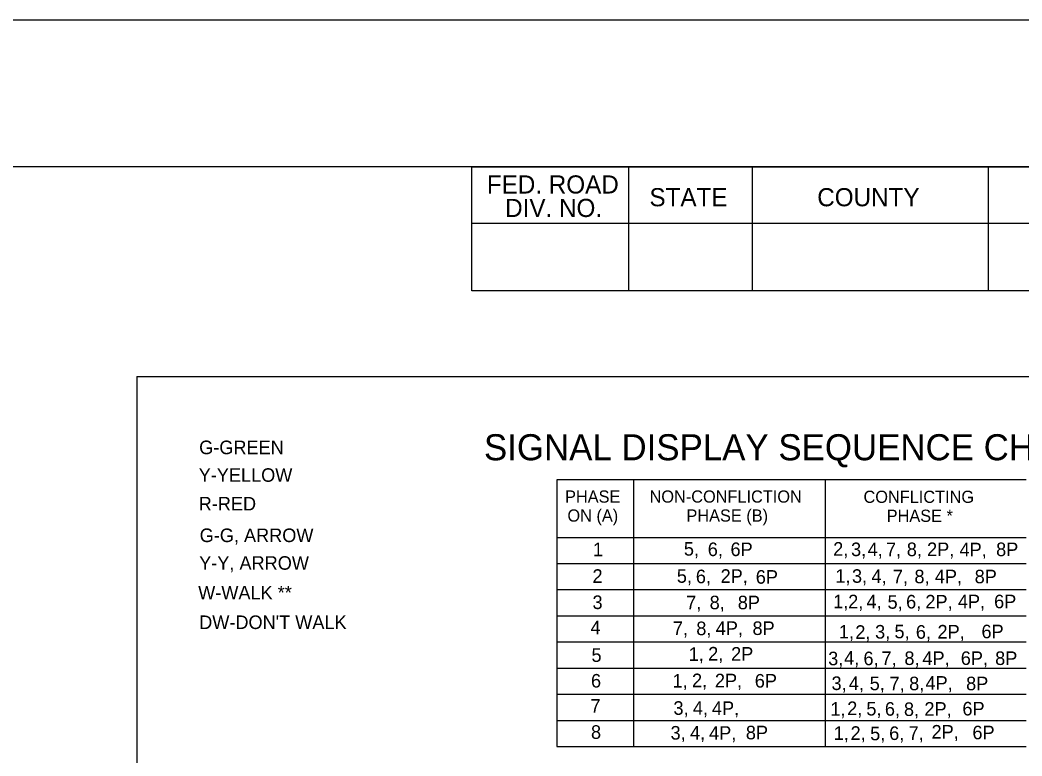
# Model space of a CAD drawing. Extents: x 0 to 3.01, y -0.05 to 1.83.
# Drawn here: x 2.2522 to 2.6475, y 1.5432 to 1.8333 of the extents above; entities that cross this region are included whole.
import ezdxf

# ---------------------------------------------------------------- set-up
doc = ezdxf.new("R2010")
doc.units = 0
for name, color, linetype in [('RD_SHT_IplotShp', 7, 'Continuous'), ('TR_TS_Border', 7, 'Continuous'), ('TR_TS_Phase1', 7, 'Continuous'), ('TR_TS_Phase2', 7, 'Continuous'), ('TR_TS_Phase3', 7, 'Continuous'), ('TR_TS_Phase4', 7, 'Continuous'), ('TR_TS_Phase5', 7, 'Continuous'), ('TR_TS_Phase6', 7, 'Continuous'), ('TR_TS_Phase7', 7, 'Continuous'), ('TR_TS_Phase8', 7, 'Continuous')]:
    doc.layers.add(name, color=color, linetype=linetype)

msp = doc.modelspace()

# ---------------------------------------------------------------- linework, layer by layer
at = {"layer": 'RD_SHT_IplotShp'}
msp.add_lwpolyline([(0, 0), (3, 0), (3, 1.83333), (0, 1.83333)], close=True, dxfattribs=at)
at = {"layer": 'TR_TS_Border'}
for p, q in [((2.94187, 1.83333), (0.031, 1.83333)), ((2.96235, 1.7754), (0.16861, 1.7754)), ((2.49245, 1.72662), (2.49245, 1.7754)), ((2.54123, 1.72662), (2.54123, 1.7754)), ((2.63434, 1.72662), (2.63434, 1.7754)), ((2.43041, 1.75323), (2.96235, 1.75323)), ((2.29837, 1.6928), (2.29837, 1.26344)), ((2.29837, 1.6928), (2.90748, 1.6928)), ((2.46395, 1.65209), (2.46395, 1.54691)), ((2.6492, 1.65209), (2.46395, 1.65209)), ((2.4942, 1.65209), (2.4942, 1.54691)), ((2.56979, 1.65209), (2.56979, 1.54691)), ((2.46395, 1.62937), (2.6492, 1.62937)), ((2.46395, 1.61906), (2.6492, 1.61906)), ((2.46395, 1.60876), (2.6492, 1.60876)), ((2.46395, 1.59845), (2.6492, 1.59845)), ((2.46395, 1.58814), (2.6492, 1.58814)), ((2.46395, 1.57783), (2.6492, 1.57783)), ((2.46395, 1.56753), (2.6492, 1.56753)), ((2.46395, 1.55722), (2.6492, 1.55722)), ((2.46395, 1.54691), (2.6492, 1.54691))]:
    msp.add_line(p, q, dxfattribs=at)
msp.add_lwpolyline([(2.96235, 1.7754), (2.96235, 1.72662), (2.43041, 1.72662), (2.43041, 1.7754)], close=True, dxfattribs=at)

# ---------------------------------------------------------------- texts
for s, height, p in [('FED. ROAD', 0.007148, (2.43639, 1.76494)), ('STATE', 0.007148, (2.50053, 1.75991)), ('COUNTY', 0.007148, (2.56672, 1.75991)), ('DIV. NO.', 0.007148, (2.44361, 1.75569)), ('SIGNAL DISPLAY SEQUENCE CHART', 0.0102811, (2.43525, 1.65976)), ('G-GREEN', 0.005347, (2.3229, 1.66217)), ('Y-YELLOW', 0.005347, (2.32271, 1.65127)), ('R-RED', 0.005347, (2.32271, 1.63997)), ('PHASE', 0.004812, (2.46724, 1.64305)), ('NON-CONFLICTION', 0.0048122, (2.50057, 1.64306)), ('CONFLICTING', 0.0048122, (2.58497, 1.64296)), ('ON (A)', 0.004812, (2.46818, 1.63557)), ('PHASE (B)', 0.004812, (2.51513, 1.63557)), ('PHASE *', 0.004812, (2.59412, 1.63548)), ('G-G, ARROW', 0.005347, (2.3231, 1.62751)), ('Y-Y, ARROW', 0.005347, (2.3229, 1.6166)), ('W-WALK **', 0.005347, (2.32251, 1.60491)), ("DW-DON'T WALK", 0.0053469, (2.3229, 1.59323))]:
    msp.add_text(s, height=height, dxfattribs=at).set_placement(p)
at = {"layer": 'TR_TS_Phase1'}
for s, height, p in [('1', 0.00535, (2.47825, 1.62195)), ('1,', 0.005347, (2.57387, 1.61148)), ('1,', 0.005347, (2.57302, 1.60143)), ('1,', 0.005347, (2.57527, 1.5895)), ('1,', 0.005347, (2.51601, 1.58067)), ('1,', 0.005347, (2.50962, 1.57015)), ('1,', 0.005347, (2.57189, 1.55907)), ('1,', 0.005347, (2.57321, 1.54949))]:
    msp.add_text(s, height=height, dxfattribs=at).set_placement(p)
at = {"layer": 'TR_TS_Phase2'}
for s, height, p in [('2,', 0.005347, (2.57301, 1.62214)), ('2P,', 0.005347, (2.61004, 1.62199)), ('2', 0.00535, (2.47806, 1.61144)), ('2P,', 0.005347, (2.5286, 1.61144)), ('2,', 0.005347, (2.57893, 1.60139)), ('2P,', 0.005347, (2.60938, 1.60133)), ('2,', 0.005347, (2.58175, 1.58936)), ('2P,', 0.005347, (2.61417, 1.58949)), ('2,', 0.005347, (2.5237, 1.58082)), ('2P', 0.005347, (2.53274, 1.58076)), ('2,', 0.005347, (2.51732, 1.5703)), ('2P,', 0.005347, (2.52635, 1.57024)), ('2,', 0.005347, (2.57855, 1.55931)), ('2P,', 0.005347, (2.609, 1.55906)), ('2,', 0.005347, (2.57987, 1.54954)), ('2P,', 0.005347, (2.61182, 1.55004))]:
    msp.add_text(s, height=height, dxfattribs=at).set_placement(p)
at = {"layer": 'TR_TS_Phase3'}
for s, height, p in [('3,', 0.005347, (2.58006, 1.62197)), ('3,', 0.005347, (2.58043, 1.61145)), ('3', 0.00535, (2.47806, 1.60111)), ('3,', 0.005347, (2.58954, 1.58947)), ('3,', 0.005347, (2.57104, 1.57895)), ('3,', 0.005347, (2.57236, 1.56918)), ('3,', 0.005347, (2.50999, 1.55941)), ('3,', 0.005347, (2.50886, 1.54964))]:
    msp.add_text(s, height=height, dxfattribs=at).set_placement(p)
at = {"layer": 'TR_TS_Phase4'}
for s, height, p in [('4,', 0.005347, (2.58661, 1.62199)), ('4P,', 0.005347, (2.62286, 1.6219)), ('4,', 0.005347, (2.58811, 1.61137)), ('4P,', 0.005347, (2.61309, 1.61129)), ('4,', 0.005347, (2.58614, 1.60142)), ('4P,', 0.005347, (2.6222, 1.60143)), ('4', 0.00535, (2.47728, 1.59118)), ('4P,', 0.005347, (2.52668, 1.59091)), ('4,', 0.005347, (2.57731, 1.57916)), ('4P,', 0.005347, (2.60821, 1.57907)), ('4,', 0.005347, (2.57919, 1.5692)), ('4P,', 0.005347, (2.60943, 1.56931)), ('4,', 0.005347, (2.51766, 1.55943)), ('4P,', 0.005347, (2.52518, 1.55935)), ('4,', 0.005347, (2.51654, 1.54967)), ('4P,', 0.005347, (2.52405, 1.54958))]:
    msp.add_text(s, height=height, dxfattribs=at).set_placement(p)
at = {"layer": 'TR_TS_Phase5'}
for s, height, p in [('5,', 0.005347, (2.51411, 1.62216)), ('5,', 0.005347, (2.51133, 1.61146)), ('5,', 0.005347, (2.59446, 1.60122)), ('5,', 0.005347, (2.59718, 1.58957)), ('5', 0.00535, (2.47767, 1.58027)), ('5,', 0.005347, (2.58741, 1.5691)), ('5,', 0.005347, (2.5861, 1.55914)), ('5,', 0.005347, (2.5876, 1.54937))]:
    msp.add_text(s, height=height, dxfattribs=at).set_placement(p)
at = {"layer": 'TR_TS_Phase6'}
for s, height, p in [('6,', 0.005347, (2.52353, 1.62199)), ('6P', 0.005347, (2.53251, 1.62199)), ('6,', 0.005347, (2.51884, 1.61129)), ('6P', 0.005347, (2.54247, 1.6111)), ('6,', 0.005347, (2.60177, 1.60133)), ('6P', 0.005347, (2.63649, 1.60142)), ('6,', 0.005347, (2.60562, 1.5894)), ('6P', 0.005347, (2.63151, 1.58959)), ('6,', 0.005347, (2.58496, 1.57897)), ('6P,', 0.005347, (2.62334, 1.57907)), ('6', 0.00535, (2.47747, 1.57015)), ('6P', 0.005347, (2.54208, 1.57015)), ('6,', 0.005347, (2.59341, 1.55906)), ('6P', 0.005347, (2.62399, 1.55916)), ('6,', 0.005347, (2.5951, 1.54948)), ('6P', 0.005347, (2.62794, 1.54976))]:
    msp.add_text(s, height=height, dxfattribs=at).set_placement(p)
at = {"layer": 'TR_TS_Phase7'}
for s, height, p in [('7,', 0.005347, (2.59384, 1.62195)), ('7,', 0.005347, (2.59656, 1.61124)), ('7,', 0.005347, (2.51503, 1.60102)), ('7,', 0.005347, (2.50977, 1.59086)), ('7,', 0.005347, (2.59205, 1.57903)), ('7,', 0.005347, (2.59525, 1.56907)), ('7', 0.00535, (2.47728, 1.56025)), ('7,', 0.005347, (2.60276, 1.54953))]:
    msp.add_text(s, height=height, dxfattribs=at).set_placement(p)
at = {"layer": 'TR_TS_Phase8'}
for s, height, p in [('8,', 0.005347, (2.60205, 1.62197)), ('8P', 0.005347, (2.63728, 1.62197)), ('8,', 0.005347, (2.60506, 1.61126)), ('8P', 0.005347, (2.62882, 1.61126)), ('8,', 0.005347, (2.52428, 1.60102)), ('8P', 0.005347, (2.53537, 1.60102)), ('8,', 0.005347, (2.51902, 1.59081)), ('8P', 0.005347, (2.54119, 1.59088)), ('8,', 0.005347, (2.60111, 1.57905)), ('8P', 0.005347, (2.6369, 1.57905)), ('8,', 0.005347, (2.60299, 1.56909)), ('8P', 0.005347, (2.62544, 1.56909)), ('8,', 0.005347, (2.60093, 1.55895)), ('8', 0.00535, (2.47747, 1.54993)), ('8P', 0.005347, (2.53856, 1.54974))]:
    msp.add_text(s, height=height, dxfattribs=at).set_placement(p)

doc.saveas('drawing.dxf')
